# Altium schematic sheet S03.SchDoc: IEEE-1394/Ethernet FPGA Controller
size 381 x 254 mm; Revision: 3.2; SheetNumber: 3; SheetTotal: 10
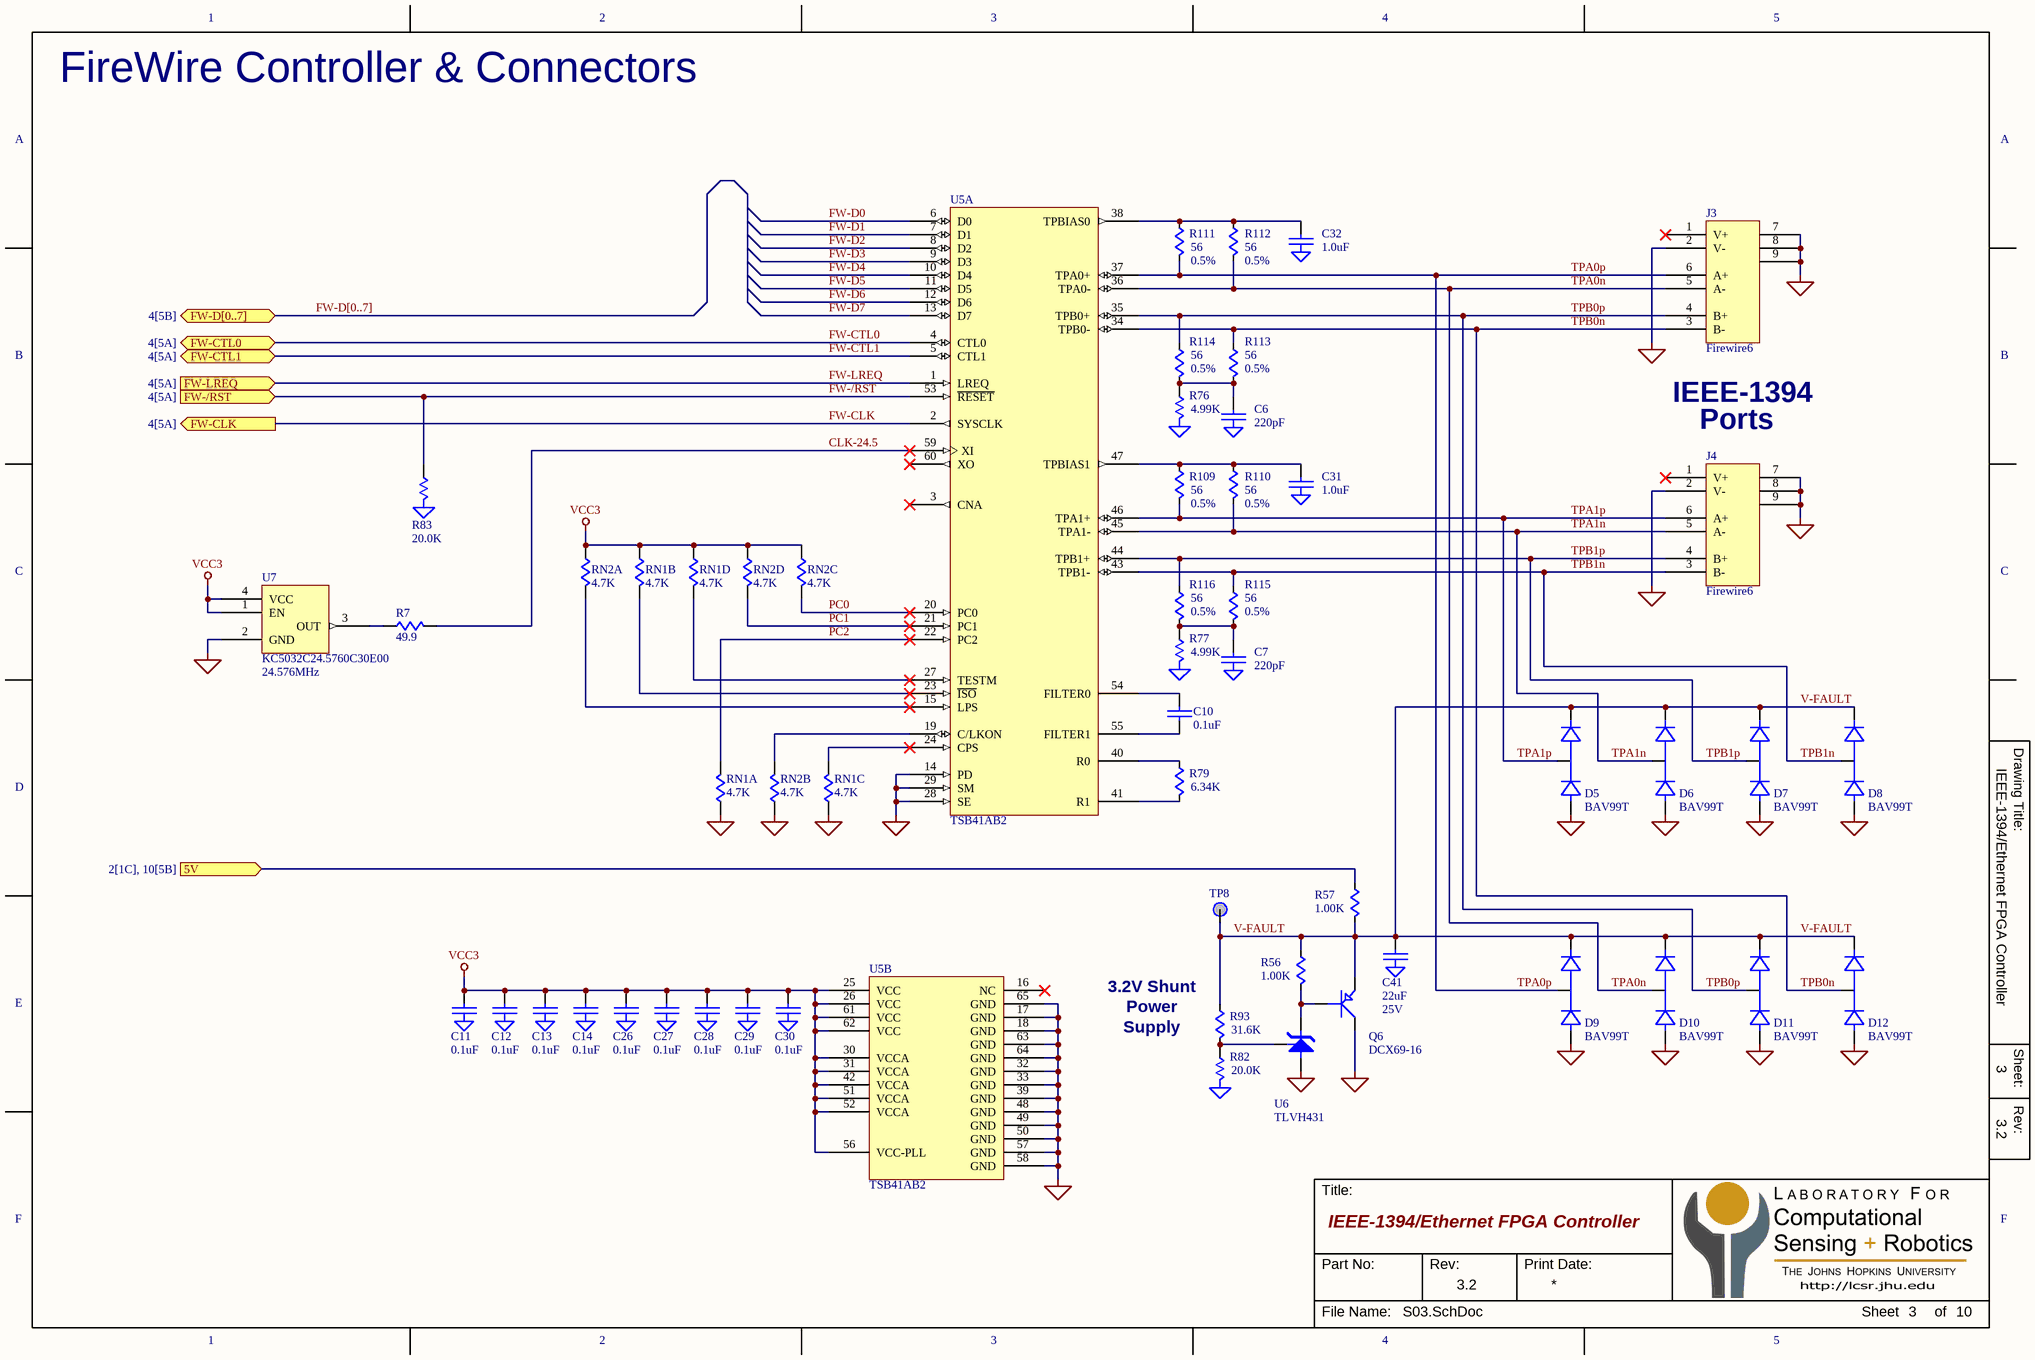
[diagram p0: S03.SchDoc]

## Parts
C6  220pF  [C0603]
C7  220pF  [C0603]
C10  0.1uF  [C0402]
C11  0.1uF  [C0402]
C12  0.1uF  [C0402]
C13  0.1uF  [C0402]
C14  0.1uF  [C0402]
C26  0.1uF  [C0402]
C27  0.1uF  [C0402]
C28  0.1uF  [C0402]
C29  0.1uF  [C0402]
C30  0.1uF  [C0402]
C31  1.0uF  [C0402]
C32  1.0uF  [C0402]
C41  22uF  [C0805]
D5  BAV99T  [SOT-523]
D6  BAV99T  [SOT-523]
D7  BAV99T  [SOT-523]
D8  BAV99T  [SOT-523]
D9  BAV99T  [SOT-523]
D10  BAV99T  [SOT-523]
D11  BAV99T  [SOT-523]
D12  BAV99T  [SOT-523]
J3  Firewire6  [Firewire6-RA]
J4  Firewire6  [Firewire6-RA]
Q6  DCX69-16  [SOT-89]
R7  49.9  [R0201]
R56  1.00K  [R0402]
R57  1.00K  [R0402]
R76  4.99K  [R0402]
R77  4.99K  [R0402]
R79  6.34K  [R0402]
R82  20.0K  [R0402]
R83  20.0K  [R0402]
R93  31.6K  [R0402]
R109  56  Toll: 0.5%  [R0603]
R110  56  Toll: 0.5%  [R0603]
R111  56  Toll: 0.5%  [R0603]
R112  56  Toll: 0.5%  [R0603]
R113  56  Toll: 0.5%  [R0603]
R114  56  Toll: 0.5%  [R0603]
R115  56  Toll: 0.5%  [R0603]
R116  56  Toll: 0.5%  [R0603]
RN1  4.7K  [RN-742C083]  (parts A,B,C,D of 4)
RN2  4.7K  [RN-742C083]  (parts A,B,C,D of 4)
TP8  PAD  [PAD25-SM]  (value not drawn)  (no BOM)
U5  TSB41AB2  [PQFP-65]  (parts A,B of 2)
U6  TLVH431  [SC70-6]
U7  KC5032C24.5760C30E00  Freq: 24.576MHz  [OSC-3x5MM]

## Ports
5V (in, see 2[1C], 10[5B]), FW-/RST (in, see 4[5A]), FW-CLK (out, see 4[5A]), FW-CTL0 (bidir, see 4[5A]), FW-CTL1 (bidir, see 4[5A]), FW-D[0..7] (bidir, see 4[5B]), FW-LREQ (in, see 4[5A])

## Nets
GND: C6.2(GND) C7.2(GND) C11.2(GND) C12.2(GND) C13.2(GND) C14.2(GND) C26.2(GND) C27.2(GND) C28.2(GND) C29.2(GND) C30.2(GND) C31.2(GND) C32.2(GND) C41.2(GND) D5.1(A) D6.1(A) D7.1(A) D8.1(A) D9.1(A) D10.1(A) D11.1(A) D12.1(A) J3.2(V-) J3.7(CHASIS) J3.8(CHASIS) J3.9(CHASIS) J4.2(V-) J4.7(CHASIS) J4.8(CHASIS) J4.9(CHASIS) Q6.3(C) R76.2(GND) R77.2(GND) R82.2(GND) R83.2(GND) RN1.1 RN1.3 RN2.2 U5.14(PD) U5.17(GND) U5.18(GND) U5.28(SE) U5.29(SM) U5.32(GND) U5.33(GND) U5.39(GND) U5.48(GND) U5.49(GND) U5.50(GND) U5.57(GND) U5.58(GND) U5.63(GND) U5.64(GND) U5.65(GND) U6.6(A) U7.2(GND)
VCC3: C11.1 C12.1 C13.1 C14.1 C26.1 C27.1 C28.1 C29.1 C30.1 RN1.2 RN1.4 RN2.1 RN2.3 RN2.4 U5.25(VCC) U5.26(VCC) U5.30(VCCA) U5.31(VCCA) U5.42(VCCA) U5.51(VCCA) U5.52(VCCA) U5.56(VCC-PLL) U5.61(VCC) U5.62(VCC) U7.1(EN) U7.4(VCC)
5V: R57.1 ; port 5V
CLK-24.5: R7.2 U5.59(XI)
FW-/RST: R83.1 U5.53(~{RESET}) ; port FW-/RST
FW-CLK: U5.2(SYSCLK) ; port FW-CLK
FW-CTL0: U5.4(CTL0) ; port FW-CTL0
FW-CTL1: U5.5(CTL1) ; port FW-CTL1
FW-D0: U5.6(D0)
FW-D1: U5.7(D1)
FW-D2: U5.8(D2)
FW-D3: U5.9(D3)
FW-D4: U5.10(D4)
FW-D5: U5.11(D5)
FW-D6: U5.12(D6)
FW-D7: U5.13(D7)
FW-LREQ: U5.1(LREQ) ; port FW-LREQ
PC0: RN2.6 U5.20(PC0)
PC1: RN2.5 U5.21(PC1)
PC2: RN1.8 U5.22(PC2)
TPA0n: D10.3(COM) J3.5(A-) R112.2 U5.36(TPA0-)
TPA0p: D9.3(COM) J3.6(A+) R111.2 U5.37(TPA0+)
TPA1n: D6.3(COM) J4.5(A-) R110.2 U5.45(TPA1-)
TPA1p: D5.3(COM) J4.6(A+) R109.2 U5.46(TPA1+)
TPB0n: D12.3(COM) J3.3(B-) R113.1 U5.34(TPB0-)
TPB0p: D11.3(COM) J3.4(B+) R114.1 U5.35(TPB0+)
TPB1n: D8.3(COM) J4.3(B-) R115.1 U5.43(TPB1-)
TPB1p: D7.3(COM) J4.4(B+) R116.1 U5.44(TPB1+)
V-FAULT: C41.1 D5.2(C) D6.2(C) D7.2(C) D8.2(C) D9.2(C) D10.2(C) D11.2(C) D12.2(C) Q6.2(E) R56.1 R57.2 R93.1 TP8.1
NetC6_1: C6.1 R76.1 R113.2 R114.2
NetC7_1: C7.1 R77.1 R115.2 R116.2
NetC10_1: C10.1 U5.54(FILTER0)
NetC10_2: C10.2 U5.55(FILTER1)
NetC31_1: C31.1 R109.1 R110.1 U5.47(TPBIAS1)
NetC32_1: C32.1 R111.1 R112.1 U5.38(TPBIAS0)
NetQ6_1: Q6.1(B) R56.2 U6.1(C)
NetR7_1: R7.1 U7.3(OUT)
NetR79_1: R79.1 U5.40(R0)
NetR79_2: R79.2 U5.41(R1)
NetR82_1: R82.1 R93.2 U6.3(ADJ)
NetRN1_5: RN1.5 U5.27(TESTM)
NetRN1_6: RN1.6 U5.24(CPS)
NetRN1_7: RN1.7 U5.23(~{ISO})
NetRN2_7: RN2.7 U5.19(C/LKON)
NetRN2_8: RN2.8 U5.15(LPS)

Not connected (* = marked no-connect by the designer): J3 1(V+)*; J4 1(V+)*; U5 3(CNA)* 16(NC)* 60(XO)*

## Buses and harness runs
bus FW-D[0..7] = port FW-D[0..7]

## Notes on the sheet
- FireWire Controller & Connectors
- IEEE-1394
- (near J4) Ports
- (near R93) 3.2V Shunt
- Power
- Supply

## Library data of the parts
C6 C7 C11-C14 C26-C32 C41 = CAP-GND
C10 = CAP
D5-D12 = DIODE-2/SER
Q6 = PNP-SM
R7 = R
R56 R57 R79 R93 R109-R116 = R-MINI
R76 R77 R82 R83 = R-GND
RN1 RN2 = RN-DISC-SM-4X
U5 = TSB41AB2: IEEE 1394a-2000 Two-port Transceiver/Arbiter
U6 = TLVH431-SC70
U7 = OSCILATOR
